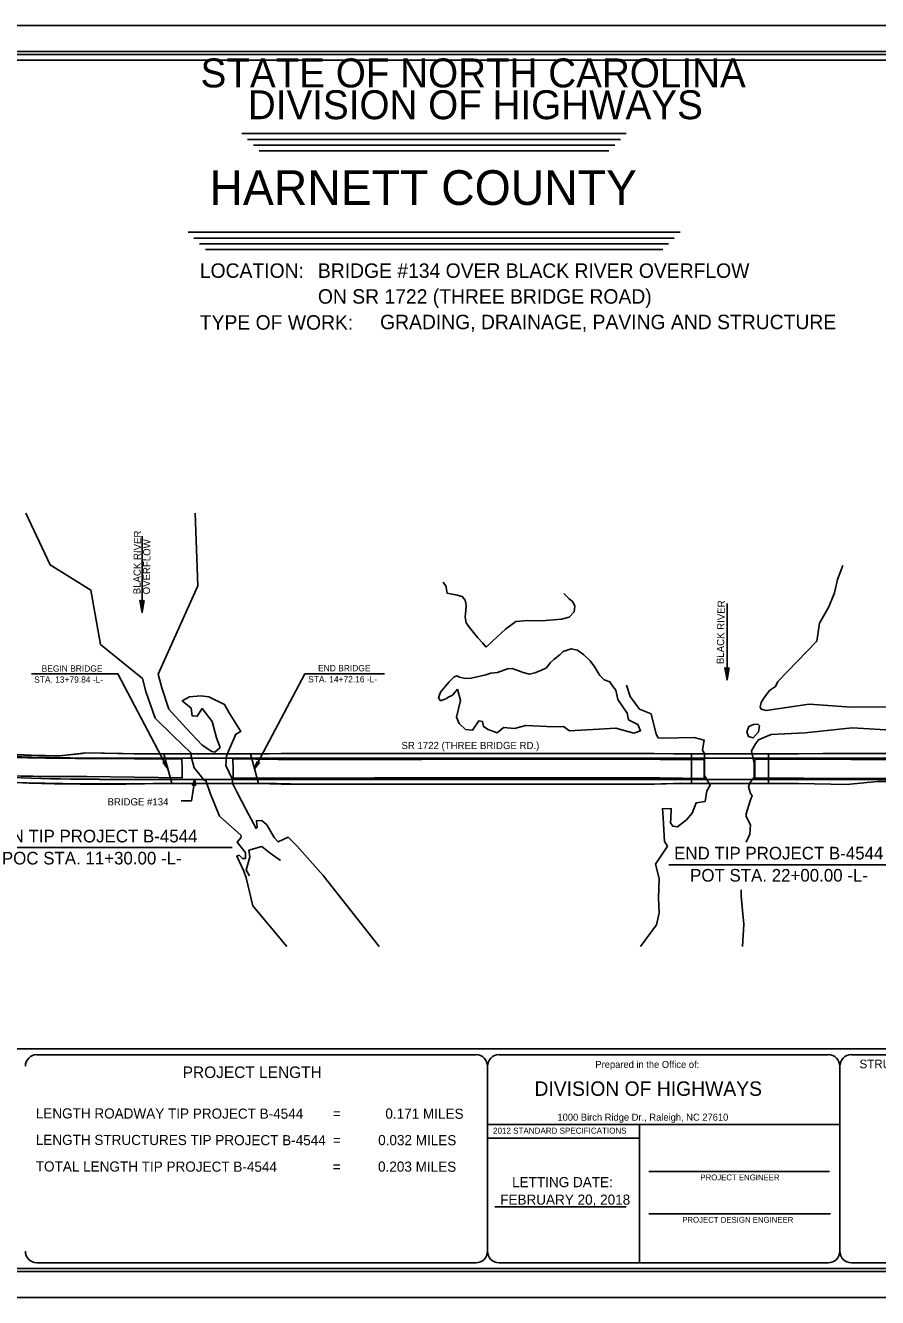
# Model space of a CAD drawing. Extents: x 0 to 2021, y 0 to 1321.
# Drawn here: x 675 to 1560, y 0 to 1321 of the extents above; entities that cross this region are included whole.
import ezdxf

# ---------------------------------------------------------------- set-up
doc = ezdxf.new("R2010")
doc.units = 0
for name, color, linetype in [('Arrowhead Terminators CELL', 7, 'Continuous'), ('Default', 7, 'Continuous'), ('Dimension Lines', 7, 'Continuous'), ('Exist Hydro Stream or Body of Water', 7, 'Continuous'), ('Exist Roads EOP', 7, 'Continuous'), ('Prop EOT', 7, 'Continuous'), ('Sheet Data Field CELL', 7, 'Continuous'), ('Sheet Plot Border Inside CELL', 7, 'Continuous'), ('Sheet Plot Border Outside CELL', 7, 'Continuous'), ('Sheet Title CELL', 7, 'Continuous'), ('Text', 7, 'Continuous')]:
    doc.layers.add(name, color=color, linetype=linetype)

msp = doc.modelspace()

# ---------------------------------------------------------------- linework, layer by layer
at = {"layer": 'Arrowhead Terminators CELL'}
for points in [[(850.5, 537.9), (848, 532), (851.1, 531.5)], [(850.5, 537.9), (850.4, 537.9), (850.5, 537.9)], [(850.5, 537.9), (850.4, 537.8), (850.5, 537.8)]]:
    msp.add_lwpolyline(points, close=True, dxfattribs=at)
at = {"layer": 'Default'}
for p, q in [((795.7, 711.1), (795.7, 790.4)), ((1403.5, 641.2), (1403.5, 720.4)), ((737.4, 565.4), (710.2, 562.3)), ((737.3, 565.4), (795.1, 564.4)), ((787.3, 564.4), (737.4, 565.4)), ((818.6, 564.4), (787.3, 564.4)), ((795.1, 564.4), (818.5, 564.4)), ((818.5, 564.4), (826.8, 533.5)), ((818.5, 564.4), (826.8, 533.5)), ((908.5, 564.4), (818.5, 564.4)), ((916.7, 533.5), (908.4, 564.4)), ((908.4, 564.4), (915.3, 564.4)), ((927.3, 564.4), (908.4, 564.4)), ((908.5, 564.4), (916.8, 533.5)), ((915.3, 564.4), (940.3, 564.9)), ((927.3, 564.4), (956.4, 564.9)), ((940.3, 564.9), (1327.8, 564.9)), ((956.4, 564.9), (1322.9, 564.9)), ((1322.9, 564.9), (1347.9, 564.4)), ((1327.8, 564.9), (1352.8, 564.4)), ((1347.9, 564.4), (1366.7, 564.4)), ((1352.8, 564.4), (1366.6, 564.4)), ((1366.6, 564.4), (1366.6, 533.5)), ((1366.6, 564.4), (1366.6, 533.5)), ((1477.9, 564.4), (1446.5, 564.4)), ((1446.6, 533.5), (1446.6, 564.4)), ((1446.6, 564.4), (1477.9, 564.4)), ((1477.9, 564.4), (1502.9, 564.9)), ((1477.9, 564.4), (1502.9, 564.9)), ((1502.9, 564.9), (1613.5, 564.9)), ((1502.9, 564.9), (1613.5, 564.9)), ((751.5, 532.9), (778.8, 532.9)), ((778.8, 532.9), (808, 533.5)), ((826.8, 533.5), (807.6, 533.5)), ((808, 533.5), (826.9, 533.5)), ((826.8, 533.5), (916.8, 533.5)), ((919.7, 533.5), (900.9, 533.5)), ((935.5, 533.5), (908.4, 533.5)), ((940.3, 532.9), (916.7, 533.5)), ((916.7, 533.5), (916.7, 533.5)), ((935.5, 533.5), (964.7, 532.9)), ((1327.8, 532.9), (940.3, 532.9)), ((964.7, 532.9), (1322.9, 532.9)), ((1322.9, 532.9), (1347.9, 533.5)), ((1352.8, 533.5), (1327.8, 532.9)), ((1347.9, 533.5), (1366.7, 533.5)), ((1366.6, 533.5), (1352.8, 533.5)), ((1446.5, 533.5), (1477.9, 533.5)), ((1477.9, 533.5), (1446.6, 533.5)), ((1527.9, 532.5), (1477.9, 533.5)), ((1477.9, 533.5), (1527.9, 532.5)), ((1559.9, 535.9), (1527.9, 532.5)), ((1527.9, 532.5), (1559.9, 535.9)), ((1641.6, 535.9), (1559.9, 535.9))]:
    msp.add_line(p, q, dxfattribs=at)
for points in [[(797.9, 723.7), (795.7, 711.1), (793.5, 723.8), (795.7, 722.2)], [(1405.7, 653.8), (1403.5, 641.2), (1401.3, 653.9), (1403.5, 652.3)], [(820.1, 556.6), (822.6, 548.9), (817.6, 555.4), (819.4, 555.1)], [(915.2, 556.6), (912.6, 548.9), (917.6, 555.4), (915.9, 555.1)]]:
    msp.add_lwpolyline(points, close=True, dxfattribs=at)
for centre, radius, start, end in [((733.6, 2481.6), 1919.4, 265.7307, 269.2997), ((751.5, 2891), 2329, 266.0471, 268.9838), ((-31.9, 7212.3), 6691.3, 276.36675, 276.6009), ((751.5, 2891), 2358, 267.4051, 270), ((760.5, 3797.9), 3264.7, 268.1837, 270.8273)]:
    msp.add_arc(centre, radius, start, end, dxfattribs=at)
at = {"layer": 'Dimension Lines'}
for p, q in [((770.6, 647.4), (680.8, 647.4)), ((822.6, 548.9), (770.6, 647.4)), ((912.6, 548.9), (964.7, 647.4)), ((964.7, 647.4), (1047.7, 647.4)), ((850.5, 537.9), (847, 515.7)), ((847, 515.7), (836.4, 515.7)), ((889.2, 467.2), (610.1, 467.1)), ((1608.3, 449.3), (1343, 449.3))]:
    msp.add_line(p, q, dxfattribs=at)
at = {"layer": 'Exist Hydro Stream or Body of Water'}
msp.add_line((939.4, 453.7), (928.8, 461.4), dxfattribs=at)
for points in [[(796.1, 642.8), (752.5, 678.1), (742.6, 734.4), (700.4, 760.6), (674.8, 814.4)], [(851, 814.4), (853.8, 738.9), (812.4, 647)], [(1456.1, 639.7), (1496.7, 681.5), (1499.6, 700.1), (1509.4, 717), (1515.3, 731.6), (1518.4, 745.6), (1523.7, 760)], [(1153.3, 675.1), (1149.5, 679.8), (1144.5, 685), (1139.9, 690.3), (1135.8, 695.5), (1132.5, 700.6), (1131.5, 706.3), (1132.2, 713.5), (1132.3, 718.7), (1131.3, 724), (1128.4, 727.8), (1121.8, 729.4), (1115.9, 730.4), (1112.6, 731.4), (1112.1, 734.6), (1111.6, 738.1), (1108.5, 742.6)], [(1153.3, 675.1), (1159.7, 681.3), (1173.2, 693.8), (1183.9, 701.7), (1196.6, 702.8), (1210.6, 702.7), (1231.4, 704.4), (1239.6, 706.4), (1244.8, 711.9), (1245.2, 717.8), (1243.2, 722.1), (1239.4, 725.5), (1233.8, 730.8)], [(1153, 646.5), (1158.2, 648.1), (1165, 648.8), (1175.3, 652.6), (1180.4, 653.1), (1186.1, 651.1), (1191.7, 648.9), (1198.1, 647.3), (1203.8, 648.6), (1209.9, 651), (1215.8, 653.7), (1219.7, 658.8), (1223.8, 662.9), (1229.6, 667.2), (1233.3, 670.6), (1241.7, 673.5), (1248, 672), (1254.6, 667.2), (1261.3, 660.9), (1266.2, 654.6), (1268.4, 650.4), (1271.2, 645.7), (1275.8, 641.3), (1281.6, 639.1), (1284.3, 635.3), (1287.9, 630.5)], [(901.4, 464.1), (894.5, 472.8), (898.3, 477.3), (898.7, 478.7), (898.5, 480), (876, 499.6), (866.6, 523.8), (861.8, 536.7), (860.7, 536.8), (849.8, 550.1), (846.9, 561.6), (846.4, 565.6), (828, 583.3), (809.5, 601.6), (799.8, 629), (796.1, 642.8)], [(933, 477.5), (925.3, 490.8), (920.2, 495.3), (914.6, 495), (915.3, 487.9), (914.2, 487.1), (903.4, 507), (894.6, 524.3), (890.5, 532.6), (889.7, 532.7), (889.6, 537.7), (882.8, 552.4), (883.3, 561.9), (885.4, 567.2), (893.2, 584.8), (898.3, 587.5), (886.1, 607), (881.5, 615.6), (865, 623.5), (856.7, 624.7), (845, 623.8), (837.5, 619.6), (846.7, 611.9), (847.8, 603.9), (853, 603.4), (858.1, 611.5), (868.7, 598), (873, 581.2), (876.8, 571.1), (871.3, 566.3), (868.3, 566.8), (858.1, 573.4), (841.3, 591.5), (823.5, 610.7), (816.1, 633), (812.4, 647)], [(1123.3, 631.5), (1118.1, 625.4), (1114.1, 623.3), (1111.3, 621.7), (1105.9, 619.5), (1103.8, 622.7), (1105.8, 628.5), (1110.9, 634.8), (1114.9, 639.2), (1120.1, 644.5), (1123.1, 645.6), (1125.5, 644), (1131.3, 642.8), (1137.6, 642.9), (1140.9, 643.7), (1153, 646.5)], [(1382.6, 525.9), (1386, 531.8), (1380.2, 541.8), (1380.2, 547.9), (1380.1, 564.9), (1379.7, 564.8), (1378.1, 568.5), (1379.8, 578.6), (1369.3, 581.5), (1336.6, 580.6), (1332, 581), (1330, 584.9), (1324.5, 605.9), (1312.7, 610.9), (1302.7, 623.9), (1299, 635.8)], [(1429, 567.6), (1432.9, 575), (1436, 578.9), (1440.9, 581.2), (1449.4, 584.6), (1484.6, 586.2), (1533.6, 591.4), (1580.2, 588.6), (1635.2, 593.2), (1676.5, 589.5), (1680.5, 586.7), (1684, 583.8), (1733, 580.8), (1774.3, 583), (1774.8, 584.4), (1773.2, 593), (1775.8, 594.6), (1772.2, 601.2), (1772.2, 604.6), (1776.1, 613.6), (1836.6, 639), (1842.3, 644.3)], [(1636.7, 612.3), (1580.5, 613.2), (1532.6, 613), (1488.7, 616.1), (1444.2, 609.6), (1438.9, 610.9), (1437.9, 613.4), (1439, 617.7), (1441.7, 622.4), (1447.6, 630.2), (1453.7, 634.4), (1456.1, 639.7)], [(1123.3, 631.5), (1126.4, 619.7), (1122.5, 602.4), (1125.2, 595.9), (1131.9, 589.6), (1139.1, 589.2), (1145.5, 598.7), (1149.5, 598), (1150.5, 592.7), (1155.3, 589.7), (1164.6, 586.4), (1168.6, 589.4), (1171.2, 591.7), (1182.8, 590.9), (1194.3, 593.9), (1223.6, 592.6), (1233.6, 592.9), (1239.8, 588.3), (1287.8, 591), (1306.6, 585.8)], [(1310.9, 594.8), (1301.2, 599.6), (1299.7, 606.7), (1289.9, 620.8), (1287.9, 630.5)], [(1310.9, 594.8), (1313.6, 588.2), (1306.6, 585.8)], [(1431.1, 595), (1435.5, 595.2), (1437.3, 593.5), (1436.2, 587.2), (1430.7, 581), (1425.7, 582.3), (1424.1, 587.2), (1426, 592.7), (1431.1, 595)], [(1427.2, 534.3), (1431.8, 540.4), (1431.7, 548), (1431.8, 554.3), (1429, 567.6)], [(1432.3, 559.6), (1432.3, 559.6)], [(1423.3, 472.6), (1427, 480.9), (1427.9, 490.9), (1423.3, 499.5), (1423.3, 502.1), (1427.4, 515.6), (1429.5, 521.1), (1427.7, 523.4), (1425.9, 530.1), (1427.2, 534.3)], [(1341.6, 468.7), (1338.5, 473.6), (1337, 498), (1336.4, 507.6), (1345.6, 507.4), (1345.2, 497.3), (1344.6, 492.9), (1347.1, 489.4), (1352, 488.6), (1361.2, 496), (1367.3, 502.8), (1371.3, 513.6), (1380.7, 515), (1382.6, 525.9)], [(933, 477.5), (937.2, 473), (947.6, 477.8), (957, 468.7)], [(904, 435.8), (901.3, 442.8), (894.1, 458.1), (896.5, 459.2), (899.9, 455.8), (903.3, 455.8), (903.3, 461.6), (901.4, 464.1)], [(907.3, 437.9), (903.9, 443.8), (907.7, 457.6), (906.8, 464.3), (920, 468.1), (928.8, 461.4)], [(1042.2, 364.4), (984, 438.3), (957, 468.7)], [(1330.2, 387), (1333.1, 399.3), (1332.3, 414.9), (1333.1, 435.2), (1329.1, 449.8), (1341.6, 468.7)], [(904, 435.8), (910.9, 406.8), (946.2, 364.4)], [(1418, 423.2), (1418.1, 416.9), (1419.7, 401.8), (1420.8, 387.8), (1419.7, 364.4)], [(1313.7, 364.4), (1330.2, 387)]]:
    msp.add_lwpolyline(points, dxfattribs=at)
at = {"layer": 'Exist Roads EOP'}
for points in [[(739.1, 559.7), (739.1, 559.7), (788, 559.4), (837.2, 559.4), (837.4, 549.5)], [(890.2, 549.1), (890.1, 559.1), (937.1, 558.7), (986.9, 558.7), (1036.8, 558.5), (1086.3, 558.7), (1135.8, 558.8), (1185.4, 558.9), (1235.2, 559), (1284.5, 558.8), (1334.1, 558.6), (1379.6, 558.7), (1379.6, 549.2)], [(890.2, 549.1), (890.1, 559.1), (937.1, 558.7), (986.9, 558.7), (1036.8, 558.5), (1086.3, 558.7), (1135.8, 558.8), (1185.4, 558.9), (1235.2, 559), (1284.5, 558.8), (1334.1, 558.6), (1379.6, 558.7), (1379.6, 549.2)], [(1432.3, 549), (1432.3, 558.5), (1483.3, 558.8), (1532.5, 558.6), (1582.3, 558.5), (1632.3, 558.5), (1681.9, 558.6), (1731.9, 558.3), (1780.9, 558.3), (1831, 558.5), (1880.4, 558.8), (1894, 558.8)], [(738.2, 540.8), (738.2, 540.8), (787.7, 540.1), (837.5, 539.5), (837.4, 549.5)], [(890.2, 549.1), (890.3, 539.3), (937.3, 539.1), (987.3, 539.2), (1036.7, 539.5), (1086.3, 539.6), (1135.6, 539.7), (1185.3, 539.6), (1234.8, 539.7), (1284.1, 539.6), (1333.9, 539.4), (1379.7, 539), (1379.6, 549.2)], [(1432.3, 549), (1432.2, 539.3), (1483, 539.2), (1532.5, 539), (1582.6, 539.1), (1632.1, 539.3), (1681.7, 539.5), (1731.7, 539.5), (1781.1, 539.4), (1830.8, 539.3), (1880.3, 539.8), (1894, 539.9)]]:
    msp.add_lwpolyline(points, dxfattribs=at)
for points in [[(378.9, 598.8), (397.3, 594.1), (445, 583.4), (493.3, 574.8), (542, 568.5), (590.7, 564.1), (639.8, 561.6), (689.2, 560.2), (739.1, 559.7)], [(378.9, 578.8), (392.7, 575.2), (441.2, 564.2), (490.5, 555.9), (540, 549.2), (589.4, 544.9), (639, 542.3), (688.6, 541.1), (738.2, 540.8)]]:
    msp.add_spline(points, degree=3, dxfattribs=at)
at = {"layer": 'Prop EOT'}
for p, q in [((751.5, 559.9), (1641.6, 559.9)), ((751.5, 537.9), (1641.6, 537.9))]:
    msp.add_line(p, q, dxfattribs=at)
for radius in [2331, 2353]:
    msp.add_arc((751.5, 2891), radius, 266.0471, 270, dxfattribs=at)
at = {"layer": 'Sheet Plot Border Inside CELL'}
msp.add_lwpolyline([(15.6, 26.9), (2015.8, 26.9), (2015.8, 1293.7), (15.6, 1293.7)], close=True, dxfattribs=at)
at = {"layer": 'Sheet Plot Border Outside CELL'}
msp.add_lwpolyline([(2021.2, 1320.6), (0, 1320.6), (0, 0), (2021.2, 0)], close=True, dxfattribs=at)
at = {"layer": 'Sheet Title CELL'}
for p, q in [((899.4, 1208.3), (1298.8, 1208.3)), ((905.4, 1202.3), (1292.8, 1202.3)), ((911.4, 1196.3), (1286.8, 1196.3)), ((917.4, 1190.3), (1280.8, 1190.3)), ((843.5, 1105.9), (1354.7, 1105.9)), ((849.5, 1099.9), (1348.7, 1099.9)), ((855.5, 1093.9), (1342.7, 1093.9)), ((861.5, 1087.9), (1336.7, 1087.9)), ((278.5, 258.1), (1982.8, 258.1)), ((686.5, 252.1), (1142.6, 252.1)), ((1166.6, 252.1), (1508.7, 252.1)), ((1532.7, 252.1), (1772.4, 252.1)), ((1154.6, 240.1), (1154.6, 48)), ((1520.7, 48), (1520.7, 240.1)), ((1520.7, 179.6), (1154.6, 179.6)), ((1312.5, 179.6), (1312.5, 36)), ((1312.5, 165.5), (1154.6, 165.5)), ((1267, 171.1), (1267, 171.1)), ((1322.2, 130.8), (1509.8, 130.8)), ((1237, 113.6), (1237, 113.6)), ((1298.8, 94.3), (1162.2, 94.3)), ((1322.2, 86.9), (1511.1, 86.9))]:
    msp.add_line(p, q, dxfattribs=at)
for points in [[(1988.8, 1290.6), (212.4, 1290.6)], [(1982.8, 1284.6), (278.5, 1284.6)], [(212.4, 30), (1988.8, 30)], [(686.5, 36), (1142.6, 36)], [(1166.6, 36), (1508.7, 36)], [(1532.7, 36), (1772.5, 36)]]:
    msp.add_lwpolyline(points, dxfattribs=at)
for centre, major_axis, start_param, end_param in [((686.5, 240.2), (0, 12), 0, 1.570796), ((1142.6, 240.2), (0, 12), 4.712389, 6.283185), ((1166.6, 240.2), (0, 12), 0, 1.570796), ((1508.7, 240.2), (0, 12), 4.712389, 6.283185), ((1532.7, 240.2), (0, 12), 0, 1.570796), ((686.5, 48.1), (0, -12), 4.712389, 6.283185), ((1142.6, 48.1), (0, -12), 0, 1.570796), ((1166.6, 48.1), (0, -12), 4.712389, 6.283185), ((1508.7, 48.1), (0, 12), 3.141593, 4.712389), ((1532.7, 48.1), (0, -12), 4.712389, 6.283185)]:
    msp.add_ellipse(centre, major_axis=major_axis, ratio=0.999692, start_param=start_param, end_param=end_param, dxfattribs=at)
at = {"layer": 'Text'}
for p, q in [((1366.6, 533.5), (1366.6, 564.4)), ((1366.6, 564.4), (1446.6, 564.4)), ((1446.6, 564.4), (1446.6, 533.5)), ((1446.6, 533.5), (1366.6, 533.5))]:
    msp.add_line(p, q, dxfattribs=at)

# ---------------------------------------------------------------- texts
at = {"layer": 'Sheet Data Field CELL'}
for s, height, p in [('HARNETT COUNTY', 36.018, (865.7, 1134.3)), ('FEBRUARY 20, 2018', 10.505, (1167.8, 96.4))]:
    msp.add_text(s, height=height, dxfattribs=at).set_placement(p)
for s, height, rotation, p in [('BRIDGE #134 OVER BLACK RIVER OVERFLOW', 15.007, 360, (978.4, 1058.6)), ('ON SR 1722 (THREE BRIDGE ROAD)', 15.007, 360, (978.4, 1031.8)), ('GRADING, DRAINAGE, PAVING AND STRUCTURE', 15.007, 360, (1043, 1005.3)), ('LENGTH ROADWAY TIP PROJECT B-4544', 10.505, 359.915, (685.3, 186)), ('=', 10.5, 359.915, (994, 185.8)), ('0.171 MILES', 10.505, 359.915, (1048.5, 185.7)), ('LENGTH STRUCTURES TIP PROJECT B-4544', 10.505, 359.915, (685.3, 158.5)), ('=', 10.5, 359.915, (994, 158.2)), ('0.032 MILES', 10.505, 359.915, (1041, 158.2)), ('TOTAL LENGTH TIP PROJECT B-4544', 10.505, 359.915, (685.3, 130.9)), ('=', 10.5, 359.915, (993.9, 130.7)), ('0.203 MILES', 10.505, 359.915, (1040.9, 130.7))]:
    msp.add_text(s, height=height, rotation=rotation, dxfattribs=at).set_placement(p)
at = {"layer": 'Sheet Title CELL'}
for s, height, p in [('STATE OF NORTH CAROLINA', 30.015, (856.5, 1256.3)), ('DIVISION OF HIGHWAYS', 30.015, (905.6, 1223.3)), ('PROJECT LENGTH', 12.005, (837.9, 227.9)), ('STRUCTURES MANAGEMENT UNIT', 9.004, (1541.1, 238)), ('DIVISION OF HIGHWAYS', 15.007, (1203.4, 209.4)), ('2012 STANDARD SPECIFICATIONS', 6.243, (1160.4, 170.1)), ('LETTING DATE:', 10.505, (1180.2, 114.6))]:
    msp.add_text(s, height=height, dxfattribs=at).set_placement(p)
for s, height, p in [('LOCATION: ', 15.01, (855.7, 1058.6)), ('TYPE OF WORK:', 15.007, (855.7, 1004.8)), ('Prepared in the Office of:', 7.258, (1266.7, 238.4)), ('1000 Birch Ridge Dr., Raleigh, NC 27610', 7.258, (1227.3, 183.6)), ('PROJECT ENGINEER', 6.048, (1375.8, 121.7)), ('PROJECT DESIGN ENGINEER', 6.048, (1356.9, 77.7))]:
    msp.add_text(s, height=height, rotation=360, dxfattribs=at).set_placement(p)
at = {"layer": 'Text'}
for s, height, rotation, p in [('BLACK RIVER', 7.472, 89.4041, (794.1, 730.1)), ('OVERFLOW', 7.47, 89.4041, (803.9, 730)), ('BLACK RIVER', 7.472, 89.0284, (1400.1, 657.6)), ('BEGIN BRIDGE', 6.538, 0.007, (691.4, 649.7)), ('END BRIDGE', 6.54, 0.007, (978.6, 650.1)), ('STA. 13+79.84 -L-', 6.538, 0.007, (683.6, 638.3)), ('STA. 14+72.16 -L-', 6.538, 0.007, (968.3, 638.6)), ('SR 1722 (THREE BRIDGE RD.) ', 7.472, 360, (1065.2, 569.4)), ('BEGIN TIP PROJECT B-4544', 13.119, 0.007, (618.3, 472.5)), ('POC STA. 11+30.00 -L-', 13.119, 0.007, (650.1, 449.6)), ('END TIP PROJECT B-4544', 13.119, 0.007, (1348.5, 454.8)), ('POT STA. 22+00.00 -L-', 13.119, 0.007, (1365.1, 431.8))]:
    msp.add_text(s, height=height, rotation=rotation, dxfattribs=at).set_placement(p)
msp.add_text('BRIDGE #134', height=7.472, dxfattribs=at).set_placement((759.8, 510.9))

doc.saveas('drawing.dxf')
